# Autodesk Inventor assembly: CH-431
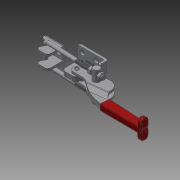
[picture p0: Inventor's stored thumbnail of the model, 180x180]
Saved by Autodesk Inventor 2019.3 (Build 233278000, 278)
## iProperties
Company: ·L?¤¤?
Created: 2010-06
Part Number: CH-431
Material: Ogólny
Description: STEP AP203
Document SubType Name: Assembly
Designer: CADENGINEERING4
Stock Number: DOCISK ZACZEPOWY KABŁĄKOWY
Sending System: SolidWorks 2005179
Preprocessor: SwSTEP 2.0
Title: CH-431.STEP
Author: ·L?¥Î?
Revision Number: ANY
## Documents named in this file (9)
- D:\Vault_2016\Projekty\Clamptek\STRONA\Latch type clamp\CH-431\CH-431.iam
- D:\Vault_2016\Projekty\Clamptek\STRONA\Latch type clamp\CH-431\431-01___.ipt
- D:\Vault_2016\Projekty\Clamptek\STRONA\Latch type clamp\CH-431\431-04___.ipt
- D:\Vault_2016\Projekty\Clamptek\STRONA\Latch type clamp\CH-431\431-06___.ipt
- D:\Vault_2016\Projekty\Clamptek\STRONA\Latch type clamp\CH-431\M5_______.ipt
- D:\Vault_2016\Projekty\Clamptek\STRONA\Latch type clamp\CH-431\431-03___.ipt
- D:\Vault_2016\Projekty\Clamptek\STRONA\Latch type clamp\CH-431\431-02___.ipt
- D:\Vault_2016\Projekty\Clamptek\STRONA\Latch type clamp\CH-431\M5___.ipt
- D:\Vault_2016\Projekty\Clamptek\STRONA\Latch type clamp\CH-431\431-05___.ipt
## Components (10 placed, 10 different names)
1. 431-01_??_1 — Zestawiające:2, Zestawiające:5, Równoległe:2, Zestawiające:8, Zestawiające:13, Zestawiające:14, Równoległe:3, Równoległe:4, Zestawiające:23
2. 431-04_??_2 — Zestawiające:9, Zestawiające:10, Zestawiające:11, Zestawiające:12, Zestawiające:13, Zestawiające:15, Zestawiające:16, Zestawiające:19, Zestawiające:20
3. 431-06_??_3 — Zestawiające:3, Zestawiające:4
4. M5????_??_4 — Zestawiające:16, Zestawiające:17
5. 431-03_??_5 — Równoległe:2, Równoległe:3, Równoległe:4
6. 431-02_??_6 — Równoległe:1, Zestawiające:1, Zestawiające:2, Zestawiające:3, Zestawiające:4, Zestawiające:5
7. M5????_??_7 — Zestawiające:20, Zestawiające:21
8. M5_??_8 — Zestawiające:19, Zestawiające:22
9. 431-05_??_9 — Równoległe:1, Zestawiające:1, Zestawiające:9, Zestawiające:10, Zestawiające:11, Zestawiające:14, Zestawiające:17, Zestawiające:18, Zestawiające:21, Zestawiające:22, Zestawiające:23
10. M5_??_10 — Zestawiające:15, Zestawiające:18
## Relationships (25: Mate 21, Flush 4)
- Równoległe:1 [Flush]: 431-02_??_6 ↔ 431-05_??_9
- Zestawiające:1 [Mate]: 431-02_??_6 ↔ 431-05_??_9
- Zestawiające:2 [Mate]: 431-01_??_1 ↔ 431-02_??_6
- Zestawiające:3 [Mate]: 431-06_??_3 ↔ 431-02_??_6
- Zestawiające:4 [Mate]: 431-06_??_3 ↔ 431-02_??_6
- Zestawiające:5 [Mate]: 431-01_??_1 ↔ 431-02_??_6
- Równoległe:2 [Flush]: 431-01_??_1 ↔ 431-03_??_5
- Zestawiające:8 [Mate]: 431-01_??_1
- Zestawiające:9 [Mate]: 431-04_??_2 ↔ 431-05_??_9
- Zestawiające:10 [Mate]: 431-04_??_2 ↔ 431-05_??_9
- Zestawiające:11 [Mate]: 431-04_??_2 ↔ 431-05_??_9
- Zestawiające:12 [Mate]: 431-04_??_2
- Zestawiające:13 [Mate]: 431-01_??_1 ↔ 431-04_??_2
- Zestawiające:14 [Mate]: 431-01_??_1 ↔ 431-05_??_9
- Zestawiające:15 [Mate]: 431-04_??_2 ↔ M5_??_10
- Zestawiające:16 [Mate]: 431-04_??_2 ↔ M5????_??_4
- Zestawiające:17 [Mate]: M5????_??_4 ↔ 431-05_??_9
- Zestawiające:18 [Mate]: 431-05_??_9 ↔ M5_??_10
- Zestawiające:19 [Mate]: 431-04_??_2 ↔ M5_??_8
- Zestawiające:20 [Mate]: 431-04_??_2 ↔ M5????_??_7
- Zestawiające:21 [Mate]: M5????_??_7 ↔ 431-05_??_9
- Zestawiające:22 [Mate]: M5_??_8 ↔ 431-05_??_9
- Równoległe:3 [Flush]: 431-01_??_1 ↔ 431-03_??_5
- Równoległe:4 [Flush]: 431-01_??_1 ↔ 431-03_??_5
- Zestawiające:23 [Mate]: 431-01_??_1 ↔ 431-05_??_9
